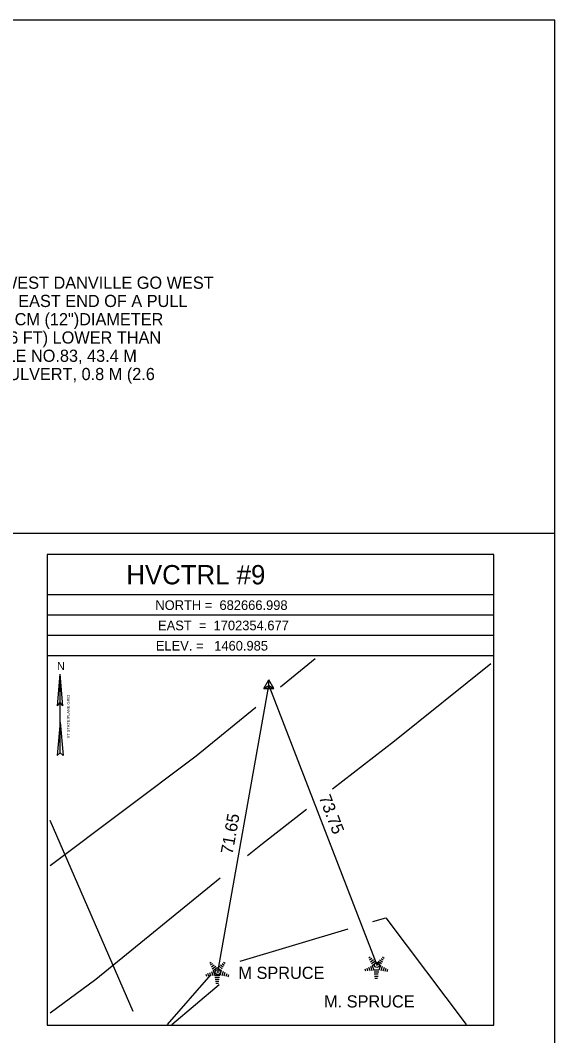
# Model space of a CAD drawing. Extents: x 1702290 to 1703620, y 686233 to 686653.
# Drawn here: x 1702798.8 to 1702930.5, y 686402.8 to 686652.9 of the extents above; entities that cross this region are included whole.
import ezdxf

# ---------------------------------------------------------------- set-up
doc = ezdxf.new("R2010")
doc.units = 0
for name, color, linetype in [('CBP', 7, 'Continuous'), ('CPSM', 7, 'Continuous'), ('DCP', 7, 'Continuous'), ('Default', 7, 'Continuous'), ('L_C', 7, 'Continuous'), ('LAWA', 7, 'Continuous'), ('LFNC', 7, 'Continuous'), ('LTC', 7, 'Continuous'), ('NBL1', 7, 'Continuous'), ('NBL2', 7, 'Continuous'), ('NNA_P', 7, 'Continuous'), ('PET', 7, 'Continuous')]:
    doc.layers.add(name, color=color, linetype=linetype)

msp = doc.modelspace()

# ---------------------------------------------------------------- linework, layer by layer
at = {"layer": 'CBP'}
for centre, radius in [((1702886.69, 686420.22), 0.625), ((1702886.69, 686420.22), 0.0833), ((1702847.5, 686418.47), 0.625), ((1702847.5, 686418.47), 0.0833)]:
    msp.add_circle(centre, radius, dxfattribs=at)
at = {"layer": 'CPSM'}
for p, q in [((1702858.83, 686488.29), (1702860.08, 686490.46)), ((1702861.33, 686488.29), (1702860.08, 686490.46)), ((1702860.08, 686489.01), (1702860.08, 686490.46)), ((1702858.83, 686488.29), (1702860.08, 686489.01)), ((1702858.83, 686488.29), (1702861.33, 686488.29)), ((1702860.08, 686489.01), (1702860.08, 686489.01)), ((1702860.08, 686489.01), (1702861.33, 686488.29))]:
    msp.add_line(p, q, dxfattribs=at)
at = {"layer": 'DCP'}
msp.add_lwpolyline([(1702826.62, 686408.76), (1702806.21, 686455.79)], dxfattribs=at)
at = {"layer": 'Default'}
for p, q in [((1702847.5, 686418.47), (1702860.08, 686489.01)), ((1702860.08, 686489.01), (1702886.69, 686420.22))]:
    msp.add_line(p, q, dxfattribs=at)
at = {"layer": 'LAWA'}
for points in [[(1702885.68, 686430.89), (1702888.85, 686431.83), (1702908.72, 686405.58)], [(1702853.03, 686421.18), (1702879.65, 686429.09)], [(1702835.09, 686405.58), (1702845.82, 686417.86)]]:
    msp.add_lwpolyline(points, dxfattribs=at)
at = {"layer": 'LFNC'}
msp.add_lwpolyline([(1702836.19, 686405.58), (1702847.82, 686415.41)], dxfattribs=at)
at = {"layer": 'LTC'}
for p, q in [((1702845.5, 686420.67), (1702845.86, 686420.93)), ((1702845.71, 686420.21), (1702846.24, 686420.59)), ((1702845.92, 686419.74), (1702846.62, 686420.25)), ((1702848.16, 686420.21), (1702848.84, 686419.72)), ((1702848.53, 686420.56), (1702849.08, 686420.16)), ((1702848.9, 686420.91), (1702849.32, 686420.61)), ((1702884.69, 686421.94), (1702885.05, 686422.2)), ((1702884.9, 686421.48), (1702885.43, 686421.86)), ((1702885.11, 686421.01), (1702885.82, 686421.52)), ((1702885.32, 686420.54), (1702886.2, 686421.18)), ((1702885.55, 686420.09), (1702886.56, 686420.82)), ((1702886.56, 686420.82), (1702887.55, 686420.1)), ((1702886.98, 686421.14), (1702887.79, 686420.55)), ((1702887.35, 686421.48), (1702888.03, 686420.99)), ((1702887.72, 686421.83), (1702888.27, 686421.43)), ((1702888.09, 686422.18), (1702888.51, 686421.88)), ((1702844.53, 686417.95), (1702844.69, 686417.48)), ((1702844.99, 686418.17), (1702845.2, 686417.52)), ((1702845.44, 686418.38), (1702845.72, 686417.55)), ((1702845.9, 686418.6), (1702846.23, 686417.58)), ((1702846.13, 686419.27), (1702847.01, 686419.91)), ((1702846.35, 686418.82), (1702847.37, 686419.55)), ((1702846.35, 686418.82), (1702846.74, 686417.63)), ((1702847.37, 686419.55), (1702848.36, 686418.83)), ((1702847.79, 686419.87), (1702848.6, 686419.28)), ((1702848.36, 686418.83), (1702847.97, 686417.63)), ((1702848.8, 686418.56), (1702848.46, 686417.52)), ((1702849.25, 686418.31), (1702848.96, 686417.42)), ((1702849.69, 686418.06), (1702849.45, 686417.33)), ((1702850.13, 686417.81), (1702849.95, 686417.23)), ((1702883.73, 686419.22), (1702883.88, 686418.75)), ((1702884.18, 686419.44), (1702884.39, 686418.79)), ((1702884.64, 686419.65), (1702884.91, 686418.82)), ((1702885.09, 686419.87), (1702885.42, 686418.85)), ((1702885.55, 686420.09), (1702885.93, 686418.9)), ((1702887.16, 686418.9), (1702885.93, 686418.9)), ((1702887.13, 686418.4), (1702885.98, 686418.4)), ((1702887.04, 686417.9), (1702886.05, 686417.9)), ((1702887.55, 686420.1), (1702887.16, 686418.9)), ((1702887.99, 686419.83), (1702887.65, 686418.79)), ((1702888.44, 686419.58), (1702888.15, 686418.69)), ((1702888.88, 686419.33), (1702888.64, 686418.6)), ((1702889.33, 686419.08), (1702889.14, 686418.5)), ((1702847.97, 686417.63), (1702846.74, 686417.63)), ((1702847.93, 686417.13), (1702846.79, 686417.13)), ((1702847.85, 686416.63), (1702846.86, 686416.63)), ((1702847.77, 686416.13), (1702846.93, 686416.13)), ((1702847.68, 686415.63), (1702847.01, 686415.63)), ((1702886.96, 686417.4), (1702886.13, 686417.4)), ((1702886.87, 686416.9), (1702886.2, 686416.9))]:
    msp.add_line(p, q, dxfattribs=at)
at = {"layer": 'NBL1'}
msp.add_lwpolyline([(1702290.49, 686232.9), (1702930.49, 686232.9), (1702930.49, 686652.9), (1702290.49, 686652.9)], close=True, dxfattribs=at)
at = {"layer": 'NBL2'}
for p, q in [((1702290.49, 686526.56), (1702930.49, 686526.56)), ((1702915.49, 686511.34), (1702805.49, 686511.34)), ((1702915.49, 686506.34), (1702805.49, 686506.34)), ((1702915.49, 686501.34), (1702805.49, 686501.34)), ((1702915.49, 686496.34), (1702805.49, 686496.34))]:
    msp.add_line(p, q, dxfattribs=at)
msp.add_lwpolyline([(1702805.49, 686405.34), (1702915.49, 686405.34), (1702915.49, 686521.34), (1702805.49, 686521.34)], close=True, dxfattribs=at)
at = {"layer": 'NNA_P'}
for p, q in [((1702807.96, 686484.05), (1702808.66, 686491.84)), ((1702808.66, 686472.47), (1702808.66, 686491.84)), ((1702809.35, 686484.05), (1702808.66, 686491.84)), ((1702807.96, 686484.05), (1702808.66, 686484.82)), ((1702809.35, 686484.05), (1702808.66, 686484.82)), ((1702808.66, 686479.99), (1702807.94, 686471.83)), ((1702808.66, 686479.99), (1702809.38, 686471.83)), ((1702808.66, 686472.47), (1702807.94, 686471.83)), ((1702808.66, 686472.47), (1702809.38, 686471.83))]:
    msp.add_line(p, q, dxfattribs=at)
at = {"layer": 'PET'}
for points in [[(1702862.96, 686488.71), (1702871.48, 686495.67)], [(1702875.76, 686463.56), (1702891.01, 686475.4), (1702914.74, 686494.47)], [(1702806.21, 686444.74), (1702842.2, 686471.74), (1702856.84, 686483.71)], [(1702854.79, 686447.14), (1702858.48, 686450.15), (1702869.37, 686458.6)], [(1702806.21, 686408.42), (1702817.46, 686416.71), (1702848.05, 686441.65)]]:
    msp.add_lwpolyline(points, dxfattribs=at)

# ---------------------------------------------------------------- texts
at = {"layer": 'Default'}
for s, p in [('TO REACH FROM THE INTERSECTION OF U.S.ROUTE 2 AND VT ROUTE 15 IN WEST DANVILLE GO WEST ', (1702644.75, 686586.77)), ('ALONG U.S.ROUTE 2 FOR 2.9 MI (4.7 KM) TO THE MARK ON THE RIGHT AT THE EAST END OF A PULL ', (1702644.75, 686582.27)), ('OUT.  THE MARK IS SET 3 CM BELOW GROUND SURFACE IN THE TOP OF A 30 CM (12")DIAMETER ', (1702644.75, 686577.77)), ('CONCRETE MONUMENT.  IT IS 9.1 M (29.9 FT) NORTH OF AND ABOUT 0.5 M (1.6 FT) LOWER THAN ', (1702644.75, 686573.27)), ('THE CENTERLINE OF U.S.ROUTE 2, 12.4 M (40.7 FT) EAST-SOUTHEAST OF POLE NO.83, 43.4 M ', (1702644.75, 686568.77)), ('(142.4 FT) WEST OF THE NORTH (INLET) END OF A 90 CM DIAMETER METAL CULVERT, 0.8 M (2.6 ', (1702644.75, 686564.27))]:
    msp.add_text(s, height=3, dxfattribs=at).set_placement(p)
for s, rotation, p in [('73.75', 291.1466, (1702872.34, 686461.49)), ('71.65', 79.8848, (1702851.12, 686447.32))]:
    msp.add_text(s, height=3, rotation=rotation, dxfattribs=at).set_placement(p)
at = {"layer": 'L_C'}
for s, p in [('M SPRUCE', (1702852.58, 686416.77)), ('M. SPRUCE', (1702873.68, 686409.73))]:
    msp.add_text(s, height=3, dxfattribs=at).set_placement(p)
at = {"layer": 'LTC'}
for p in [(1702847.25, 686418.57), (1702886.44, 686419.84)]:
    msp.add_text('.', height=1.04, rotation=270, dxfattribs=at).set_placement(p)
at = {"layer": 'NBL2'}
for s, height, p in [('     HVCTRL #9     ', 4.75, (1702816.14, 686513.96)), ('NORTH =  682666.998 ', 2.375, (1702832.11, 686507.65)), ('EAST  =  1702354.677', 2.375, (1702832.77, 686502.65)), ('ELEV. =   1460.985  ', 2.375, (1702832.22, 686497.65))]:
    msp.add_text(s, height=height, dxfattribs=at).set_placement(p)
at = {"layer": 'NNA_P'}
msp.add_text('N', height=1.97, dxfattribs=at).set_placement((1702807.89, 686492.86))
msp.add_text('VT STATE PLANE GRID', height=0.7, rotation=90.0204, dxfattribs=at).set_placement((1702811.01, 686476.03))

doc.saveas('drawing.dxf')
